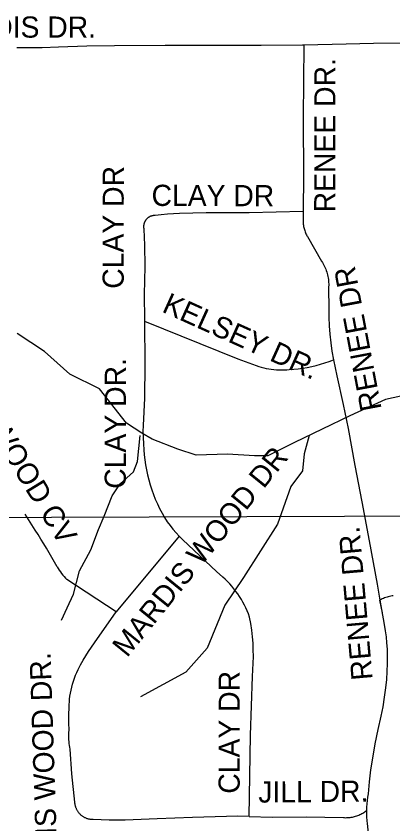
# Model space of a CAD drawing. Extents: x 1670563 to 1761545, y 515755 to 578944.
# Drawn here: x 1696673 to 1698008, y 532515 to 535375 of the extents above; entities that cross this region are included whole.
import ezdxf

# ---------------------------------------------------------------- set-up
doc = ezdxf.new("R2010")
doc.units = 0
for name, color, linetype in [('4_TwnRge', 7, 'Continuous'), ('SHP_LINE', 7, 'Continuous'), ('STREETCL', 7, 'Continuous'), ('STRNAMES', 7, 'Continuous')]:
    doc.layers.add(name, color=color, linetype=linetype)

msp = doc.modelspace()

# ---------------------------------------------------------------- linework, layer by layer
at = {"layer": '4_TwnRge'}
msp.add_lwpolyline([(1677728, 533231.8), (1683031.7, 533346.7), (1683119.4, 533342.5), (1688238.5, 533490), (1688376.1, 533487.8), (1693684.6, 533590.9), (1698873.3, 533608.2), (1704126.3, 533645.6)], dxfattribs=at)
at = {"layer": 'SHP_LINE'}
for points in [[(1697119, 533899), (1697064, 533934), (1696969, 534055), (1696863, 534107), (1696774, 534188), (1696677, 534251)], [(1698107, 534045), (1697982, 534018), (1697856, 533960), (1697659, 533865), (1697565, 533818), (1697518, 533818), (1697422, 533824), (1697311, 533821), (1697246, 533842), (1697155, 533877), (1697119, 533899)], [(1696834, 533236), (1696854, 533280), (1696877, 533329), (1696898, 533411), (1696938, 533486), (1696965, 533558), (1696985, 533605), (1697013, 533677), (1697042, 533719), (1697089, 533762), (1697103, 533798), (1697113, 533890)], [(1697711, 533890), (1697694, 533825), (1697688, 533765), (1697647, 533710), (1697599, 533576), (1697479, 533388), (1697413, 533290), (1697350, 533137), (1697275, 533052), (1697114, 532965)]]:
    msp.add_lwpolyline(points, dxfattribs=at)
at = {"layer": 'STREETCL'}
for points in [[(1698923.1, 535287.8), (1698794.5, 535286), (1698764, 535285.2), (1698748.8, 535284.4), (1698550.5, 535282.8), (1698294.1, 535280.3), (1698165.1, 535279.5), (1698094.4, 535279.5), (1698041.4, 535278.7), (1697939.5, 535277.9), (1697843, 535275.4), (1697692.3, 535272.4)], [(1697692.3, 535272.4), (1697687.8, 535272.3), (1697541.7, 535271.5), (1697354.1, 535271.4), (1697200.8, 535271.4), (1697021.4, 535269.8), (1696924, 535268.2), (1696823.6, 535264.9), (1696765, 535262.5), (1696675.4, 535262.6)], [(1697692.3, 535272.4), (1697690.6, 535016.7), (1697691.4, 534801.2), (1697690.6, 534693.7), (1697690.4, 534682.8)], [(1697690.4, 534682.8), (1697498.8, 534678.6), (1697346.4, 534678.6), (1697252.3, 534676), (1697230.6, 534675.1), (1697209, 534673.7), (1697187.4, 534671.7), (1697165.9, 534669.1), (1697164.5, 534669.1), (1697163.1, 534669.1), (1697161.7, 534669), (1697160.4, 534668.9), (1697159, 534668.8), (1697157.6, 534668.5), (1697156.3, 534668.3), (1697154.9, 534668), (1697153.6, 534667.6), (1697152.3, 534667.2), (1697151, 534666.7), (1697149.7, 534666.2), (1697148.4, 534665.7), (1697147.2, 534665.1), (1697145.9, 534664.5), (1697144.7, 534663.8), (1697143.5, 534663.1), (1697142.4, 534662.4), (1697141.2, 534661.6), (1697140.1, 534660.7), (1697139.1, 534659.9), (1697138, 534659), (1697137, 534658), (1697136, 534657), (1697135.1, 534656), (1697134.2, 534655), (1697133.3, 534653.9), (1697132.5, 534652.8), (1697131.7, 534651.7), (1697131, 534650.5), (1697130.2, 534649.3), (1697129.6, 534648.1), (1697128.9, 534646.9), (1697128.4, 534645.7), (1697127.8, 534644.4), (1697127.3, 534643.1), (1697126.9, 534641.8), (1697126.5, 534640.5), (1697126.1, 534639.1), (1697125.8, 534637.8), (1697125.5, 534636.4), (1697125.3, 534635.1), (1697125.1, 534633.7), (1697125, 534632.3), (1697124.9, 534631), (1697124.9, 534629.6), (1697124.9, 534628.2), (1697125, 534626.8), (1697125.1, 534625.4), (1697125.3, 534624.1), (1697125.5, 534622.7), (1697125.7, 534621.3), (1697127.6, 534564.2), (1697129.3, 534489.1), (1697126.7, 534389.7), (1697127.6, 534300.1), (1697127.6, 534295)], [(1697690.4, 534682.8), (1697689.8, 534653.9), (1697689.8, 534650), (1697689.9, 534646.1), (1697690.2, 534642.2), (1697690.6, 534638.3), (1697691.1, 534634.4), (1697691.8, 534630.6), (1697692.6, 534626.8), (1697693.5, 534623), (1697694.5, 534619.2), (1697695.7, 534615.5), (1697697, 534611.8), (1697698.5, 534608.2), (1697700.1, 534604.7), (1697701.7, 534601.1), (1697703.6, 534597.7), (1697705.5, 534594.3), (1697755.7, 534507.3), (1697758.5, 534502.8), (1697761.2, 534498.2), (1697763.7, 534493.5), (1697766.1, 534488.8), (1697768.3, 534483.9), (1697770.3, 534479), (1697772.1, 534474), (1697773.8, 534469), (1697775.3, 534463.9), (1697776.6, 534458.8), (1697777.8, 534453.6), (1697778.7, 534448.3), (1697779.5, 534443.1), (1697780.1, 534437.8), (1697780.5, 534432.5), (1697780.7, 534427.2), (1697780.7, 534421.9), (1697780.6, 534416.6), (1697780.2, 534411.3), (1697780.9, 534339.8), (1697781.3, 534309.4), (1697782.6, 534279), (1697784.8, 534248.7), (1697788.1, 534218.5), (1697792.2, 534188.4), (1697797.4, 534158.4)], [(1697127.6, 534295), (1697129.3, 534141.8), (1697128.4, 534022.3), (1697123.2, 533925.5), (1697122.7, 533904.1), (1697123, 533882.7), (1697124, 533861.3), (1697125.8, 533840), (1697127.1, 533821.9), (1697129, 533803.9), (1697131.6, 533786), (1697134.8, 533768.2), (1697138.5, 533750.5), (1697142.9, 533732.9), (1697147.9, 533715.5), (1697153.5, 533698.3), (1697159.7, 533681.3), (1697166.4, 533664.5), (1697173.8, 533647.9), (1697181.6, 533631.6), (1697190.1, 533615.6), (1697199.1, 533599.9), (1697208.6, 533584.5), (1697218.6, 533571.4), (1697229, 533558.6), (1697239.7, 533546), (1697250.8, 533533.8)], [(1697127.6, 534295), (1697323.9, 534215.5), (1697458.8, 534161.7), (1697524.1, 534137.5), (1697532.8, 534134.6), (1697541.5, 534132.1), (1697550.4, 534129.8), (1697559.3, 534127.8), (1697568.3, 534126.1), (1697577.3, 534124.8), (1697586.4, 534123.7), (1697595.5, 534123), (1697604.6, 534122.5), (1697613.7, 534122.4), (1697622.9, 534122.6), (1697632, 534123.1), (1697641.1, 534123.9), (1697657.1, 534124.9), (1697673.1, 534126.6), (1697689, 534128.7), (1697704.9, 534131.4), (1697720.7, 534134.6), (1697736.3, 534138.4), (1697751.8, 534142.6), (1697767.2, 534147.4), (1697782.3, 534152.6), (1697797.4, 534158.4)], [(1697797.4, 534158.4), (1697803.2, 534129.6), (1697809.9, 534101), (1697831.9, 533999.8), (1697849.2, 533915.3), (1697873.5, 533783.6), (1697898, 533656), (1697924.7, 533517.2), (1697952.2, 533364.1), (1697962.3, 533307.6)], [(1696740.4, 533555.5), (1696740.4, 533555.5), (1696705.8, 533611.2)], [(1697250.8, 533533.8), (1697027.7, 533266.2)], [(1697498.7, 532541.6), (1697503.9, 532829.4), (1697510.3, 533037.3), (1697512.3, 533060.7), (1697513.6, 533084.1), (1697514.1, 533107.6), (1697513.7, 533131.1), (1697512.6, 533154.6), (1697510.7, 533178), (1697508.1, 533201.4), (1697504.6, 533224.6), (1697500.4, 533247.7), (1697496.4, 533258.5), (1697492.1, 533269.2), (1697487.4, 533279.6), (1697482.4, 533290), (1697477, 533300.1), (1697471.2, 533310), (1697465.2, 533319.8), (1697458.8, 533329.3), (1697452, 533338.6), (1697445, 533347.7), (1697437.6, 533356.5), (1697430, 533365.1), (1697422, 533373.3), (1697413.8, 533381.4), (1697405.3, 533389.1), (1697383, 533409.1), (1697263.4, 533520.6), (1697250.8, 533533.8)], [(1697027.7, 533266.3), (1696852.6, 533380.6)], [(1697971, 533262.7), (1697962.3, 533307.6), (1697977.7, 533220.7), (1697981.2, 533199.1), (1697984, 533177.5), (1697986.1, 533155.8), (1697987.5, 533134), (1697988.2, 533112.2), (1697988.2, 533083.4), (1697987.2, 533054.7), (1697985.2, 533026), (1697982.3, 532997.4), (1697977.6, 532963.8), (1697972, 532930.3), (1697965.6, 532897), (1697954.3, 532849.3), (1697944.2, 532798.7), (1697935.4, 532747.7), (1697929.1, 532706.1), (1697924.1, 532664.3), (1697920.4, 532622.3), (1697918.5, 532610.5), (1697917, 532598.6), (1697915.9, 532586.7), (1697915.1, 532574.7), (1697914.8, 532562.7)], [(1698009.7, 533323.2), (1698005.2, 533322.5), (1698000.7, 533321.7), (1697996.2, 533320.8), (1697991.8, 533319.6), (1697987.4, 533318.4), (1697983.1, 533316.9), (1697978.8, 533315.4), (1697974.6, 533313.7), (1697970.4, 533311.8), (1697966.3, 533309.8), (1697962.3, 533307.6)], [(1696901.2, 532548.2), (1696899.7, 532549.7), (1696898.2, 532551.3), (1696896.8, 532552.9), (1696895.4, 532554.5), (1696894.1, 532556.2), (1696892.8, 532558), (1696891.6, 532559.8), (1696890.5, 532561.6), (1696889.4, 532563.5), (1696888.4, 532565.4), (1696887.4, 532567.3), (1696886.6, 532569.3), (1696885.8, 532571.3), (1696885, 532573.3), (1696884.3, 532575.3), (1696883.7, 532577.4), (1696883.2, 532579.5), (1696882.7, 532581.6), (1696882.3, 532583.7), (1696882, 532585.8), (1696881.7, 532587.9), (1696881.5, 532590.1), (1696881.4, 532592.2), (1696870.9, 532693), (1696864.9, 532780.4), (1696863.6, 532786.9), (1696862.4, 532793.4), (1696861.5, 532799.9), (1696860.8, 532806.5), (1696860.3, 532813.1), (1696860, 532819.7), (1696860, 532826.3), (1696860.1, 532832.9), (1696860.5, 532839.5), (1696861.1, 532846.1), (1696860.2, 532873.7), (1696860, 532901.4), (1696860.7, 532929), (1696862.1, 532956.6), (1696863.6, 532967.6), (1696865.5, 532978.4), (1696867.8, 532989.2), (1696870.4, 532999.9), (1696873.3, 533010.5), (1696876.6, 533021), (1696880.2, 533031.4), (1696884.1, 533041.7), (1696888.4, 533051.8), (1696893, 533061.9), (1696901.4, 533078.3), (1696910.4, 533094.5), (1696919.8, 533110.5), (1696929.7, 533126.1), (1696940.1, 533141.4), (1696950.9, 533156.4), (1697027.7, 533266.2)], [(1697498.7, 532541.6), (1697580.6, 532539.6), (1697700.7, 532540.6), (1697832.9, 532537.6), (1697836.9, 532537.4), (1697840.9, 532537.3), (1697844.8, 532537.4), (1697848.8, 532537.6), (1697852.8, 532537.9), (1697856.7, 532538.3), (1697860.7, 532538.9), (1697864.6, 532539.6), (1697868.5, 532540.5), (1697872.3, 532541.4), (1697876.2, 532542.5), (1697880, 532543.8), (1697883.7, 532545.1), (1697887.4, 532546.6), (1697891, 532548.2), (1697894.6, 532549.9), (1697898.2, 532551.8), (1697901.6, 532553.8), (1697905, 532555.8), (1697908.3, 532558), (1697911.6, 532560.3), (1697914.8, 532562.7)], [(1697914.8, 532562.7), (1697914.8, 532550.9), (1697915.1, 532539.1), (1697915.9, 532527.2), (1697917, 532515.5), (1697918.3, 532507.3), (1697920.2, 532476.8), (1697921.3, 532446.3), (1697921.6, 532415.8), (1697921.6, 532312.3), (1697922, 532172.3), (1697923.3, 532032.4), (1697924.1, 531954.2), (1697922.9, 531857.3), (1697923.1, 531808.2)], [(1697498.7, 532541.6), (1697459, 532542.5), (1697298.3, 532537.6), (1697172.7, 532533.8), (1697116.1, 532530.3), (1697059.5, 532528.6), (1697002.8, 532528.7), (1696946.1, 532530.5), (1696944, 532530.5), (1696941.8, 532530.6), (1696939.7, 532530.7), (1696937.5, 532531), (1696935.4, 532531.3), (1696933.3, 532531.6), (1696931.2, 532532.1), (1696929.1, 532532.6), (1696927, 532533.2), (1696925, 532533.8), (1696922.9, 532534.6), (1696920.9, 532535.3), (1696918.9, 532536.2), (1696917, 532537.1), (1696915.1, 532538.1), (1696913.2, 532539.2), (1696911.4, 532540.3), (1696909.6, 532541.5), (1696907.8, 532542.7), (1696906.1, 532544), (1696904.4, 532545.3), (1696902.8, 532546.7), (1696901.2, 532548.2)]]:
    msp.add_lwpolyline(points, dxfattribs=at)
for centre, radius, start, end in [((1695036.8, 532441.3), 2035.6, 28.8988, 33.1837), ((1697000.1, 533527.6), 208.2, 209.5042, 224.8949)]:
    msp.add_arc(centre, radius, start, end, dxfattribs=at)

# ---------------------------------------------------------------- texts
at = {"layer": 'STRNAMES'}
for s, rotation, p in [('MARDIS DR.', 359.9387, (1696365.7, 535299.1)), ('RENEE DR.', 89.9387, (1697804.2, 534680.1)), ('CLAY DR', 89.9387, (1697054.5, 534409.7)), ('CLAY DR', 359.8056, (1697153, 534703.1)), ('RENEE DR', 100.6784, (1697968.5, 533984.4)), ('KELSEY DR.', 335.7072, (1697186.4, 534329.5)), ('MARDIS WOOD CV', 301.5739, (1696353.1, 534271.8)), ('CLAY DR.', 89.9387, (1697061.9, 533701.7)), ('MARDIS WOOD DR', 50.9944, (1697066.3, 533101.6)), ('RENEE DR.', 94.9778, (1697936.8, 533027)), ('MARDIS WOOD DR.', 91.8896, (1696826.4, 532182.8)), ('CLAY DR', 89.9387, (1697465.4, 532622.1)), ('JILL DR.', 0.5178, (1697531.5, 532590.5))]:
    msp.add_text(s, height=75, rotation=rotation, dxfattribs=at).set_placement(p)

doc.saveas('drawing.dxf')
